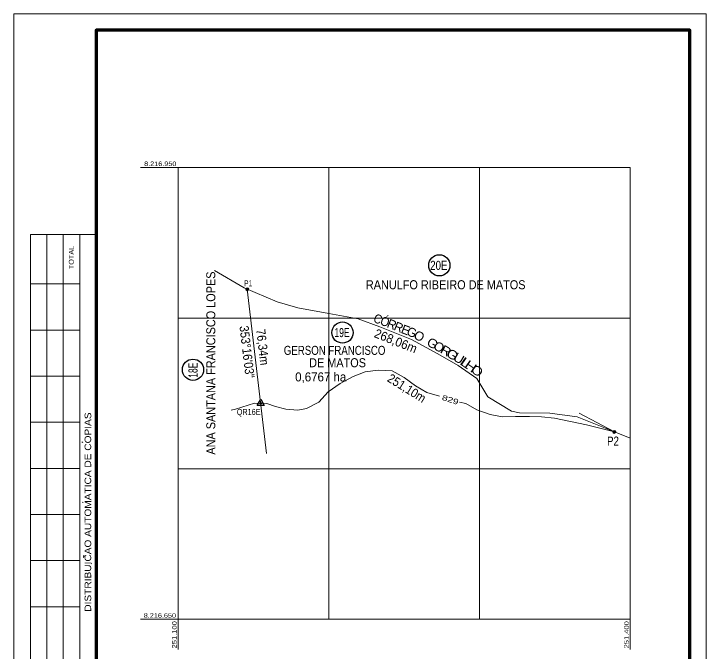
# Model space of a CAD drawing. Extents: x 250991 to 251450, y 8216402 to 8217052.
# Drawn here: x 250991 to 251450.4, y 8216628.8 to 8217052.1 of the extents above; entities that cross this region are included whole.
import ezdxf
from ezdxf.enums import TextEntityAlignment as Align

# ---------------------------------------------------------------- set-up
doc = ezdxf.new("R2010")
doc.units = 0
doc.header["$LTSCALE"] = 2.4
doc.header["$PDMODE"] = 32
doc.header["$PDSIZE"] = 1.2
for name, color, linetype, lineweight in [('1', 7, 'Continuous', 13), ('2', 7, 'Continuous', 13), ('3', 7, 'Continuous', 13), ('32', 7, 'Continuous', 13), ('34', 7, 'Continuous', 25), ('37', 7, 'Continuous', 13), ('6', 7, 'Continuous', 13)]:
    doc.layers.add(name, color=color, linetype=linetype, lineweight=lineweight)
for name, color, linetype in [('31', 7, 'Continuous'), ('33', 7, 'Continuous'), ('40', 7, 'Continuous')]:
    doc.layers.add(name, color=color, linetype=linetype)

msp = doc.modelspace()

# ---------------------------------------------------------------- hatches: boundary and pattern name
at = {"layer": '37'}
for points in [[(251146.81, 8216869.219, 1), (251144.81, 8216869.219, 1)], [(251390.407, 8216774.486, 1), (251388.407, 8216774.486, 1)]]:
    msp.add_hatch(color=256, dxfattribs=at).paths.add_polyline_path(points)

# ---------------------------------------------------------------- linework, layer by layer
at = {"layer": '1'}
for points in [[(251273.51, 8216798.08), (251265.11, 8216800.54), (251257.4, 8216805.06), (251250.05, 8216810.57), (251242.03, 8216814.98), (251232.73, 8216815.39), (251224.13, 8216814.35), (251216.14, 8216811.17), (251207.55, 8216806.68), (251199.61, 8216801), (251193.41, 8216794.2), (251185.16, 8216789.91), (251179.43, 8216788.87), (251171.36, 8216789.65), (251164.58, 8216791.21), (251158.8, 8216793.27)], [(251158.8, 8216793.27), (251150.72, 8216793.53), (251137.96, 8216789.51), (251135.17, 8216788.79)], [(251366.05, 8216786.99), (251389.43, 8216774.48), (251370.87, 8216779.05), (251349.82, 8216783.6), (251341.18, 8216784.54), (251333.13, 8216784.76), (251323.89, 8216784.65), (251314.96, 8216784.39), (251307, 8216786.03), (251298.12, 8216789.06), (251290.88, 8216793.32), (251286.68, 8216794.3)]]:
    msp.add_lwpolyline(points, dxfattribs=at)
at = {"layer": '2'}
msp.add_line((251158.7, 8216760), (251145.81, 8216869.22), dxfattribs=at)
at = {"layer": '3'}
msp.add_lwpolyline([(251124.22, 8216881.58), (251143.69, 8216870.1), (251165.79, 8216860.92), (251179.5, 8216856.78), (251200.04, 8216853.01), (251219.37, 8216849.59), (251233.83, 8216844.26), (251254.87, 8216835.85), (251272.33, 8216826.28), (251285.84, 8216818.47), (251298.27, 8216809.86), (251305.54, 8216797.65), (251321.27, 8216788.32), (251326.4, 8216787.21), (251346.52, 8216786.99), (251364.69, 8216784.54), (251382.36, 8216777.28), (251400, 8216770.29)], dxfattribs=at)
at = {"layer": '32'}
for p, q in [((251075, 8216950), (251400, 8216950)), ((251100, 8216630), (251100, 8216950)), ((251200, 8216650), (251200, 8216950)), ((251300, 8216650), (251300, 8216950)), ((251400, 8216630), (251400, 8216950)), ((251100, 8216850), (251400, 8216850)), ((251100, 8216750), (251400, 8216750)), ((251075, 8216650), (251400, 8216650))]:
    msp.add_line(p, q, dxfattribs=at)
at = {"layer": '34'}
for centre in [(251273.267, 8216885.071), (251209.048, 8216840.418), (251109.843, 8216815.718)]:
    msp.add_circle(centre, 7.04, dxfattribs=at)
at = {"layer": '37', "lineweight": 25}
msp.add_lwpolyline([(251157.16, 8216792.02), (251152.36, 8216792.02), (251154.76, 8216796.17)], close=True, dxfattribs=at)
at = {"layer": '37'}
for centre in [(251145.81, 8216869.219), (251389.407, 8216774.486)]:
    msp.add_circle(centre, 1, dxfattribs=at)
msp.add_point((251154.76, 8216793.4), dxfattribs=at)
at = {"layer": '6'}
for p, q in [((251001.92, 8216905.49), (251045.67, 8216905.49)), ((251001.92, 8216905.49), (251001.92, 8216533.61)), ((251012.85, 8216905.49), (251012.85, 8216533.61)), ((251023.8, 8216533.61), (251023.8, 8216905.49)), ((251034.72, 8216905.49), (251034.72, 8216533.61)), ((251001.92, 8216872.69), (251034.72, 8216872.69)), ((251001.92, 8216842.06), (251034.72, 8216842.06)), ((251001.92, 8216811.44), (251034.72, 8216811.44)), ((251001.92, 8216780.81), (251034.72, 8216780.81)), ((251036.72, 8216767.51), (251036.1, 8216767.74)), ((251001.92, 8216750.19), (251034.72, 8216750.19)), ((251036.95, 8216727.66), (251036.27, 8216727.89)), ((251001.92, 8216719.56), (251034.72, 8216719.56)), ((251001.92, 8216688.94), (251034.72, 8216688.94)), ((251042.25, 8216687.14), (251042.82, 8216686.89)), ((251001.92, 8216658.31), (251034.72, 8216658.31))]:
    msp.add_line(p, q, dxfattribs=at)
msp.add_lwpolyline([(250990.97, 8216402.36), (251450.35, 8216402.36), (251450.35, 8217052.06), (250990.97, 8217052.06)], close=True, dxfattribs=at)
at = {"layer": '6', "lineweight": 70}
msp.add_lwpolyline([(251045.67, 8216413.31), (251439.42, 8216413.31), (251439.42, 8217041.11), (251045.67, 8217041.11)], close=True, dxfattribs=at)
at = {"layer": '6'}
msp.add_spline([(251037.32, 8216691.09), (251037.2, 8216691.56), (251037.5, 8216691.89), (251037.6, 8216692.21), (251037.37, 8216692.61)], degree=3, dxfattribs=at)

# ---------------------------------------------------------------- texts
at = {"layer": '1', "width": 1.4}
msp.add_text('829', height=3.6, rotation=342.082, dxfattribs=at).set_placement((251280.046, 8216794.072), align=Align.CENTER)
at = {"layer": '31', "width": 0.95}
msp.add_text('0,6767 ha', height=6, dxfattribs=at).set_placement((251194.6, 8216807.97), align=Align.CENTER)
at = {"layer": '32', "width": 1.2}
for s, p in [('8.216.950', (251088.14, 8216951)), ('8.216.650', (251087.88, 8216651))]:
    msp.add_text(s, height=3, dxfattribs=at).set_placement(p, align=Align.CENTER)
at = {"layer": '32'}
for s, height, rotation, width, p in [('353°16\'03"', 6, 276.731, 0.9, (251142.736, 8216827.207)), ('76,34m', 6, 276.731, 0.9, (251153.16, 8216830.402)), ('268,06m', 6, 338.213, 0.95, (251243.332, 8216832.047)), ('251,10m', 6, 328.131, 0.9, (251250.136, 8216800.943)), ('251.100', 3, 90, 1.25, (251099, 8216639.71)), ('251.400', 3, 90, 1.25, (251399, 8216639.71))]:
    msp.add_text(s, height=height, rotation=rotation, dxfattribs=dict(at, width=width)).set_placement(p, align=Align.CENTER)
at = {"layer": '33', "width": 0.9}
msp.add_text('ANA SANTANA FRANCISCO LOPES', height=6, rotation=90, dxfattribs=at).set_placement((251124.66, 8216820.145), align=Align.CENTER)
at = {"layer": '33'}
for s, width, p in [('RANULFO RIBEIRO DE MATOS', 0.9, (251277.525, 8216869.17)), ('GERSON FRANCISCO', 0.8, (251203.805, 8216825.59)), (' DE MATOS', 0.9, (251204.76, 8216817.38))]:
    msp.add_text(s, height=6, dxfattribs=dict(at, width=width)).set_placement(p, align=Align.CENTER)
at = {"layer": '34'}
for s, width, p in [('20E', 0.8, (251272.97, 8216882.05)), ('19E', 0.7, (251208.74, 8216837.4))]:
    msp.add_text(s, height=6, dxfattribs=dict(at, width=width)).set_placement(p, align=Align.CENTER)
at = {"layer": '34', "width": 0.7}
msp.add_text('18E', height=6, rotation=90, dxfattribs=at).set_placement((251112.84, 8216815.42), align=Align.CENTER)
at = {"layer": '37'}
for s, height, width, p in [('P1', 4, 0.65, (251146.47, 8216871.08)), ('QR16E', 4, 0.75, (251146.77, 8216785.73)), ('P2', 6, 0.8, (251388.53, 8216765.37))]:
    msp.add_text(s, height=height, dxfattribs=dict(at, width=width)).set_placement(p, align=Align.CENTER)
at = {"layer": '40'}
for s, rotation, width, p in [('C', 339.766, 0.9, (251231.497, 8216846.648)), ('Ó', 338.213, 0.9, (251236.137, 8216844.892)), ('O', 331.272, 1.05, (251258.538, 8216835.437)), ('G', 331.272, 1.1, (251267.358, 8216830.596)), ('O', 331.272, 1.05, (251271.688, 8216828.227)), ('R', 329.968, 1.15, (251276.199, 8216825.637)), ('G', 329.968, 1.15, (251280.464, 8216823.169)), ('U', 329.968, 1.15, (251284.729, 8216820.717)), ('L', 325.29, 1.6, (251289.172, 8216817.772)), ('H', 325.29, 1.3, (251292.442, 8216815.509)), ('O', 325.29, 1.2, (251296.682, 8216812.569))]:
    msp.add_text(s, height=6, rotation=rotation, dxfattribs=dict(at, width=width)).set_placement(p, align=Align.CENTER)
for s, p in [('R', (251240.707, 8216843.062)), ('R', (251245.277, 8216841.232)), ('E', (251249.837, 8216839.398)), ('G', (251253.977, 8216837.756))]:
    msp.add_text(s, height=6, rotation=338.213, dxfattribs=at).set_placement(p, align=Align.CENTER)
at = {"layer": '6'}
for s, height, width, p in [('TOTAL', 3.281, 1.1, (251030.75, 8216882.49)), ('DISTRIBUICAO AUTOMATICA DE COPIAS', 4.375, 1.15, (251042.28, 8216655.04))]:
    msp.add_text(s, height=height, rotation=90, dxfattribs=dict(at, width=width)).set_placement(p)

doc.saveas('drawing.dxf')
